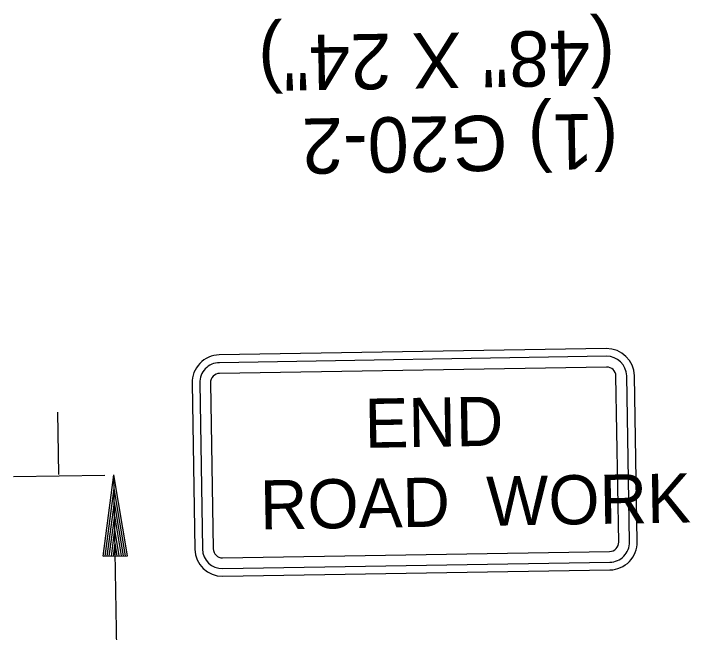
# Model space of a CAD drawing. Extents: x 1676063 to 1678026, y 228339 to 229904.
# Drawn here: x 1677671.3 to 1677744.8, y 229197.1 to 229264.2 of the extents above; entities that cross this region are included whole.
import ezdxf

# ---------------------------------------------------------------- set-up
doc = ezdxf.new("R2010")
doc.units = 0
for name, color, linetype in [('P_TC_Signs_Temporary', 7, 'Continuous'), ('R_Annotation', 7, 'Continuous'), ('R_Draft', 7, 'Continuous')]:
    doc.layers.add(name, color=color, linetype=linetype)

msp = doc.modelspace()

# ---------------------------------------------------------------- linework, layer by layer
at = {"layer": 'P_TC_Signs_Temporary'}
for p, q in [((1677735.619, 229227.899), (1677693.625, 229227.203)), ((1677735.633, 229227.066), (1677693.638, 229226.37)), ((1677735.652, 229225.899), (1677693.658, 229225.203)), ((1677736.967, 229206.919), (1677736.668, 229224.916)), ((1677738.133, 229206.938), (1677737.835, 229224.935)), ((1677738.966, 229206.952), (1677738.668, 229224.949)), ((1677690.675, 229224.154), (1677690.973, 229206.156)), ((1677691.508, 229224.168), (1677691.806, 229206.17)), ((1677692.674, 229224.187), (1677692.973, 229206.189)), ((1677693.989, 229205.206), (1677735.983, 229205.902)), ((1677694.009, 229204.04), (1677736.003, 229204.736)), ((1677694.022, 229203.206), (1677736.017, 229203.902))]:
    msp.add_line(p, q, dxfattribs=at)
for centre, radius, start, end in [((1677735.668, 229224.9), 3, 0.94971, 90.94971), ((1677693.674, 229224.203), 3, 90.94971, 180.94971), ((1677735.668, 229224.9), 2.167, 0.94971, 90.94971), ((1677693.674, 229224.203), 2.167, 90.94971, 180.94971), ((1677735.668, 229224.9), 1, 0.94971, 90.94971), ((1677693.674, 229224.203), 1, 90.94971, 180.94971), ((1677735.967, 229206.902), 1, 270.94971, 0.94971), ((1677735.967, 229206.902), 2.167, 270.94971, 0.94971), ((1677735.967, 229206.902), 3, 270.94971, 0.94971), ((1677693.973, 229206.206), 3, 180.94971, 270.94971), ((1677693.973, 229206.206), 2.167, 180.94971, 270.94971), ((1677693.973, 229206.206), 1, 180.94971, 270.94971)]:
    msp.add_arc(centre, radius, start, end, dxfattribs=at)
at = {"layer": 'R_Draft'}
for p, q in [((1677676.232, 229214.243), (1677676.12, 229221)), ((1677671.307, 229214.018), (1677681.207, 229214.182)), ((1677681.033, 229205.384), (1677682.207, 229214.206)), ((1677683.698, 229124.237), (1677682.207, 229214.206)), ((1677683.673, 229205.428), (1677682.207, 229214.206)), ((1677681.253, 229205.388), (1677682.231, 229212.736)), ((1677683.453, 229205.424), (1677682.231, 229212.736)), ((1677681.476, 229205.391), (1677682.256, 229211.222)), ((1677683.23, 229205.42), (1677682.256, 229211.222)), ((1677681.696, 229205.395), (1677682.281, 229209.759)), ((1677683.01, 229205.417), (1677682.281, 229209.759)), ((1677681.926, 229205.399), (1677682.305, 229208.266)), ((1677682.783, 229205.413), (1677682.305, 229208.266)), ((1677682.146, 229205.402), (1677682.33, 229206.796)), ((1677682.56, 229205.409), (1677682.33, 229206.796)), ((1677681.033, 229205.384), (1677683.673, 229205.428))]:
    msp.add_line(p, q, dxfattribs=at)

# ---------------------------------------------------------------- texts
at = {"layer": 'P_TC_Signs_Temporary'}
for s, p in [('END', (1677709.434, 229217.13)), ('ROAD  WORK', (1677698.086, 229208.274))]:
    msp.add_text(s, height=5.3333, rotation=0.94971, dxfattribs=at).set_placement(p)
at = {"layer": 'R_Annotation'}
for s, p in [('(48" X 24")', (1677736.508, 229262.451)), ('(1) G20-2', (1677736.872, 229253.398))]:
    msp.add_text(s, height=6, rotation=180.94971, dxfattribs=at).set_placement(p)

doc.saveas('drawing.dxf')
